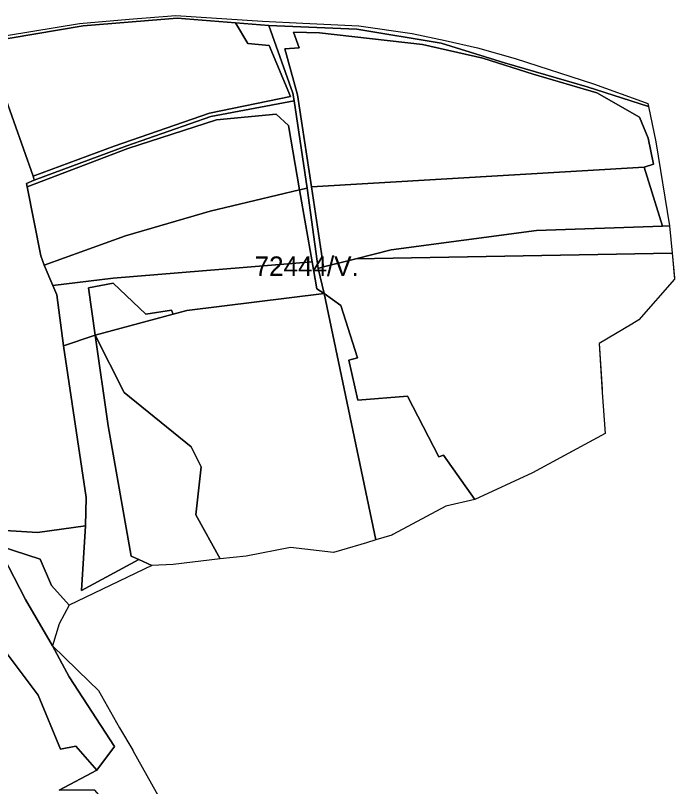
# Model space of a CAD drawing. Extents: x -502026 to -497664, y -1143484 to -1138019.
# Drawn here: x -498809.4 to -498538.5, y -1143009.2 to -1142692.1 of the extents above; entities that cross this region are included whole.
import ezdxf

# ---------------------------------------------------------------- set-up
doc = ezdxf.new("R2010")
doc.units = 0
for name, color, linetype in [('37', 7, 'Continuous'), ('43', 7, 'Continuous'), ('55', 7, 'Continuous'), ('62', 7, 'Continuous'), ('7', 7, 'Continuous')]:
    doc.layers.add(name, color=color, linetype=linetype)

msp = doc.modelspace()

# ---------------------------------------------------------------- linework, layer by layer
at = {"layer": '37'}
for points in [[(-498718.92, -1142695.09), (-498713.81, -1142703.58), (-498705.09, -1142704.42), (-498696.25, -1142725.42), (-498729.58, -1142732.34), (-498768.81, -1142745.89), (-498802.13, -1142758.2), (-498813.95, -1142724.49), (-498821.39, -1142703.09), (-498781.57, -1142696.34), (-498742.86, -1142693.2)], [(-498705.26, -1142696.31), (-498695.29, -1142724.07), (-498694.74, -1142727.26), (-498729.03, -1142733.61), (-498763.62, -1142745.69), (-498801.6, -1142759.91), (-498802.13, -1142758.2), (-498768.81, -1142745.89), (-498729.58, -1142732.34), (-498696.25, -1142725.42), (-498705.09, -1142704.42), (-498713.81, -1142703.58), (-498718.92, -1142695.09)], [(-498689.51, -1142763.07), (-498692.58, -1142763.81), (-498697.18, -1142737.32), (-498702.24, -1142732.72), (-498726.79, -1142734.99), (-498763.17, -1142746.87), (-498804.49, -1142762.6), (-498804.77, -1142761.15), (-498801.6, -1142759.91), (-498763.62, -1142745.69), (-498729.03, -1142733.61), (-498694.74, -1142727.26)], [(-498684.98, -1142796.13), (-498682.48, -1142806.42), (-498685.5, -1142804.59), (-498687.43, -1142793.47), (-498692.58, -1142763.81), (-498689.51, -1142763.07)], [(-498620.54, -1142891.09), (-498633.43, -1142872.89), (-498635.38, -1142873.58), (-498648.17, -1142848.67), (-498668.62, -1142850.27), (-498672.39, -1142833.81), (-498668.73, -1142832.9), (-498675.63, -1142811.33), (-498682.48, -1142806.42), (-498684.98, -1142796.13), (-498682.69, -1142795.55), (-498669.5, -1142792.2), (-498539.49, -1142789.87), (-498538.46, -1142800.61), (-498553.18, -1142817.3), (-498556.04, -1142819.02), (-498569.42, -1142827.03), (-498568.19, -1142847.09), (-498567.01, -1142864.08), (-498596.8, -1142880.25)], [(-498682.48, -1142806.42), (-498738.91, -1142813.5), (-498744.54, -1142815.01), (-498745.19, -1142813.3), (-498755.7, -1142814.9), (-498769.18, -1142802.21), (-498779.35, -1142804.13), (-498776.57, -1142823.57), (-498776.95, -1142823.67), (-498789.64, -1142827.96), (-498792.37, -1142807.01), (-498793.96, -1142803.22), (-498769.13, -1142800.19), (-498687.43, -1142793.47), (-498685.5, -1142804.59)], [(-498744.54, -1142815.01), (-498776.57, -1142823.57), (-498779.35, -1142804.13), (-498769.18, -1142802.21), (-498755.7, -1142814.9), (-498745.19, -1142813.3)], [(-498661.29, -1142907.8), (-498665.06, -1142908.97), (-498675.36, -1142911.98), (-498678.58, -1142912.92), (-498696.35, -1142910.88), (-498714.56, -1142914.4), (-498725.16, -1142915.61), (-498735.26, -1142897.4), (-498732.97, -1142877.75), (-498737.2, -1142869.52), (-498764.73, -1142847.12), (-498776.57, -1142823.57), (-498744.54, -1142815.01), (-498738.91, -1142813.5), (-498682.48, -1142806.42)]]:
    msp.add_lwpolyline(points, close=True, dxfattribs=at)
at = {"layer": '43'}
for points in [[(-498549.19, -1142729.61), (-498546.14, -1142744.05), (-498540.56, -1142778.63), (-498543.41, -1142778.73), (-498550.98, -1142754.52), (-498547.08, -1142753.27), (-498549.29, -1142742.61), (-498552.87, -1142733.96), (-498570.42, -1142723.95), (-498596.62, -1142716.28), (-498617.21, -1142709.65), (-498642, -1142704.01), (-498684.4, -1142699.32), (-498695.11, -1142698.99), (-498692.74, -1142705.36), (-498698.7, -1142705.83), (-498693.46, -1142724.73), (-498687.69, -1142762.65), (-498682.69, -1142795.55), (-498684.98, -1142796.13), (-498689.51, -1142763.07), (-498694.74, -1142727.26), (-498695.29, -1142724.07), (-498705.26, -1142696.31), (-498668.99, -1142697.77), (-498634.43, -1142703.56), (-498608.31, -1142711.62), (-498574.36, -1142721.48)], [(-498550.98, -1142754.52), (-498687.69, -1142762.65), (-498693.46, -1142724.73), (-498698.7, -1142705.83), (-498692.74, -1142705.36), (-498695.11, -1142698.99), (-498684.4, -1142699.32), (-498642, -1142704.01), (-498617.21, -1142709.65), (-498596.62, -1142716.28), (-498570.42, -1142723.95), (-498552.87, -1142733.96), (-498549.29, -1142742.61), (-498547.08, -1142753.27)], [(-498802.13, -1142758.2), (-498801.6, -1142759.91), (-498804.77, -1142761.15), (-498804.49, -1142762.6), (-498798.94, -1142790.97), (-498797.52, -1142794.75), (-498793.96, -1142803.22), (-498792.37, -1142807.01), (-498789.64, -1142827.96), (-498780.24, -1142890.32), (-498780.62, -1142901.94), (-498800.33, -1142904.75), (-498820.36, -1142903.49), (-498821.78, -1142906.01), (-498834.84, -1142851.68), (-498848.87, -1142798.61), (-498873.05, -1142803.85), (-498861.35, -1142788.01), (-498855.04, -1142762.74), (-498851.29, -1142731.06), (-498851.63, -1142727.92), (-498813.95, -1142724.49)], [(-498543.41, -1142778.73), (-498595.19, -1142780.53), (-498654.87, -1142788.49), (-498669.5, -1142792.2), (-498682.69, -1142795.55), (-498687.69, -1142762.65), (-498550.98, -1142754.52)], [(-498620.54, -1142891.09), (-498632.52, -1142893.85), (-498654.24, -1142905.53), (-498654.67, -1142905.76), (-498661.29, -1142907.8), (-498682.48, -1142806.42), (-498675.63, -1142811.33), (-498668.73, -1142832.9), (-498672.39, -1142833.81), (-498668.62, -1142850.27), (-498648.17, -1142848.67), (-498635.38, -1142873.58), (-498633.43, -1142872.89)], [(-498787.24, -1142934.61), (-498791.45, -1142942.27), (-498794.1, -1142951.32), (-498787.26, -1142964.11), (-498768.58, -1142992.66), (-498775.87, -1143002.39), (-498784.58, -1142992.53), (-498790.85, -1142993.81), (-498800.06, -1142971.66), (-498819.9, -1142945.25), (-498832.51, -1142915.83), (-498821.31, -1142908.5), (-498799.17, -1142915.67), (-498794.56, -1142926.55)], [(-498754.3, -1143029.46), (-498767.94, -1143020.96), (-498776.77, -1143010.71), (-498791.36, -1143010.71), (-498775.87, -1143002.39), (-498768.58, -1142992.66), (-498787.26, -1142964.11), (-498794.1, -1142951.32), (-498779.04, -1142965.98), (-498775.21, -1142969.7), (-498766.65, -1142985.07), (-498761.16, -1142994.24), (-498761.09, -1142994.36), (-498745.81, -1143021.85)]]:
    msp.add_lwpolyline(points, close=True, dxfattribs=at)
for points in [[(-498820.36, -1142903.49), (-498800.33, -1142904.75), (-498780.62, -1142901.94), (-498782.14, -1142928.54), (-498758.69, -1142915.86), (-498753.29, -1142918.31), (-498787.24, -1142934.61), (-498794.56, -1142926.55), (-498799.17, -1142915.67), (-498821.31, -1142908.5)], [(-498819.9, -1142945.25), (-498800.06, -1142971.66), (-498790.85, -1142993.81), (-498784.58, -1142992.53), (-498775.87, -1143002.39), (-498791.36, -1143010.71)]]:
    msp.add_lwpolyline(points, dxfattribs=at)
at = {"layer": '55'}
msp.add_lwpolyline([(-498549.19, -1142729.61), (-498574.36, -1142721.48), (-498608.31, -1142711.62), (-498634.43, -1142703.56), (-498668.99, -1142697.77), (-498705.26, -1142696.31), (-498718.92, -1142695.09), (-498742.86, -1142693.2), (-498781.57, -1142696.34), (-498821.39, -1142703.09), (-498822.28, -1142701.93), (-498783.08, -1142695.45), (-498762.56, -1142693.69), (-498743.39, -1142692.1), (-498707.76, -1142694.47), (-498691.29, -1142695.25), (-498668.23, -1142696.44), (-498646.3, -1142699.53), (-498632.79, -1142702.37), (-498619.48, -1142705.38), (-498603.94, -1142709.81), (-498571.77, -1142720.19), (-498550.49, -1142727.91), (-498549.47, -1142728.28)], close=True, dxfattribs=at)
at = {"layer": '62'}
for points in [[(-498822.28, -1142701.93), (-498783.08, -1142695.45), (-498762.56, -1142693.69), (-498743.39, -1142692.1), (-498707.76, -1142694.47), (-498691.29, -1142695.25), (-498668.23, -1142696.44), (-498646.3, -1142699.53), (-498632.79, -1142702.37), (-498619.48, -1142705.38), (-498603.94, -1142709.81), (-498571.77, -1142720.19), (-498550.49, -1142727.91), (-498549.47, -1142728.28), (-498549.19, -1142729.61), (-498546.14, -1142744.05), (-498540.56, -1142778.63), (-498539.49, -1142789.87), (-498538.52, -1142799.98), (-498538.46, -1142800.61), (-498553.18, -1142817.3), (-498556.04, -1142819.02), (-498569.42, -1142827.03), (-498568.27, -1142845.85), (-498568.19, -1142847.09), (-498567.01, -1142864.08), (-498583.68, -1142873.13), (-498596.8, -1142880.25), (-498620.54, -1142891.09), (-498632.52, -1142893.85), (-498654.24, -1142905.53), (-498654.67, -1142905.76), (-498661.29, -1142907.8), (-498665.06, -1142908.97), (-498675.36, -1142911.98), (-498678.58, -1142912.92), (-498696.35, -1142910.88), (-498714.56, -1142914.4), (-498725.16, -1142915.61), (-498744.47, -1142917.86), (-498753.29, -1142918.31), (-498787.24, -1142934.61), (-498791.45, -1142942.27), (-498794.1, -1142951.32), (-498805.26, -1142932.33), (-498816.85, -1142909.94)], [(-498816.85, -1142909.94), (-498805.26, -1142932.33), (-498794.1, -1142951.32), (-498779.04, -1142965.98), (-498775.21, -1142969.7), (-498766.65, -1142985.07), (-498761.16, -1142994.24), (-498761.09, -1142994.36), (-498745.81, -1143021.85)]]:
    msp.add_lwpolyline(points, dxfattribs=at)
at = {"layer": '7'}
for points in [[(-498692.58, -1142763.81), (-498729.26, -1142772.59), (-498764.19, -1142782.74), (-498797.52, -1142794.75), (-498798.94, -1142790.97), (-498804.49, -1142762.6), (-498763.17, -1142746.87), (-498726.79, -1142734.99), (-498702.24, -1142732.72), (-498697.18, -1142737.32)], [(-498687.43, -1142793.47), (-498769.13, -1142800.19), (-498793.96, -1142803.22), (-498797.52, -1142794.75), (-498764.19, -1142782.74), (-498729.26, -1142772.59), (-498692.58, -1142763.81)], [(-498539.49, -1142789.87), (-498669.5, -1142792.2), (-498654.87, -1142788.49), (-498595.19, -1142780.53), (-498543.41, -1142778.73), (-498540.56, -1142778.63)], [(-498758.69, -1142915.86), (-498782.14, -1142928.54), (-498780.62, -1142901.94), (-498780.24, -1142890.32), (-498789.64, -1142827.96), (-498776.95, -1142823.67), (-498776.57, -1142823.57), (-498771.24, -1142860.8), (-498761.79, -1142914.45)], [(-498725.16, -1142915.61), (-498744.47, -1142917.86), (-498753.29, -1142918.31), (-498758.69, -1142915.86), (-498761.79, -1142914.45), (-498771.24, -1142860.8), (-498776.57, -1142823.57), (-498764.73, -1142847.12), (-498737.2, -1142869.52), (-498732.97, -1142877.75), (-498735.26, -1142897.4)]]:
    msp.add_lwpolyline(points, close=True, dxfattribs=at)

# ---------------------------------------------------------------- texts
at = {"layer": '62'}
msp.add_text('72444/V.', height=8, dxfattribs=at).set_placement((-498711.07, -1142799.21))

doc.saveas('drawing.dxf')
